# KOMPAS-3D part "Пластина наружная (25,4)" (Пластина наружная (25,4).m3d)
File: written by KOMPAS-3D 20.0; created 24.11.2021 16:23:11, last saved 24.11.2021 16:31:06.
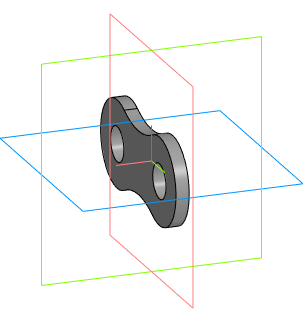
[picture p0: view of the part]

Document properties: Полное имя файла: C:\!WORK!\ЗИГ-18.240.00\Цепь\Пластина наружная (25,4).m3d

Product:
- Part/product: Пластина наружная (25,4)
    Материал: Сталь 45  ГОСТ 1050-2013 (density 7810 kg/m3)
    Масса: 0.0150352

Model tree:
1. Эскиз:1
2. Элемент выдавливания:1  (labels: Сталь 45  ГОСТ 1050-2013)
     Расстояние 1 = 3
